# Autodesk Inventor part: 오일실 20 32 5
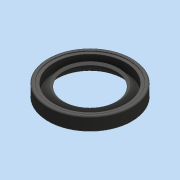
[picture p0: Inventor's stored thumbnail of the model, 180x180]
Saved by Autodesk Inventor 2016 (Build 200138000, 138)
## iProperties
Created: 2024-08
Part Number: 오일실 20 32 5
Material: 일반
Description: 오일 실 - 비스프링, 조립 GA
Document SubType Name: Modeling
Designer: pc-7
Density: 1 g/cm^3
Appearance: 기본값
Author: jhkim
Sending System: Autodesk Inventor 2025
Preprocessor: ST-DEVELOPER v20
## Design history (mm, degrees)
node "오일실 20 32 51"
node "솔리드1"
body "Solid1"
